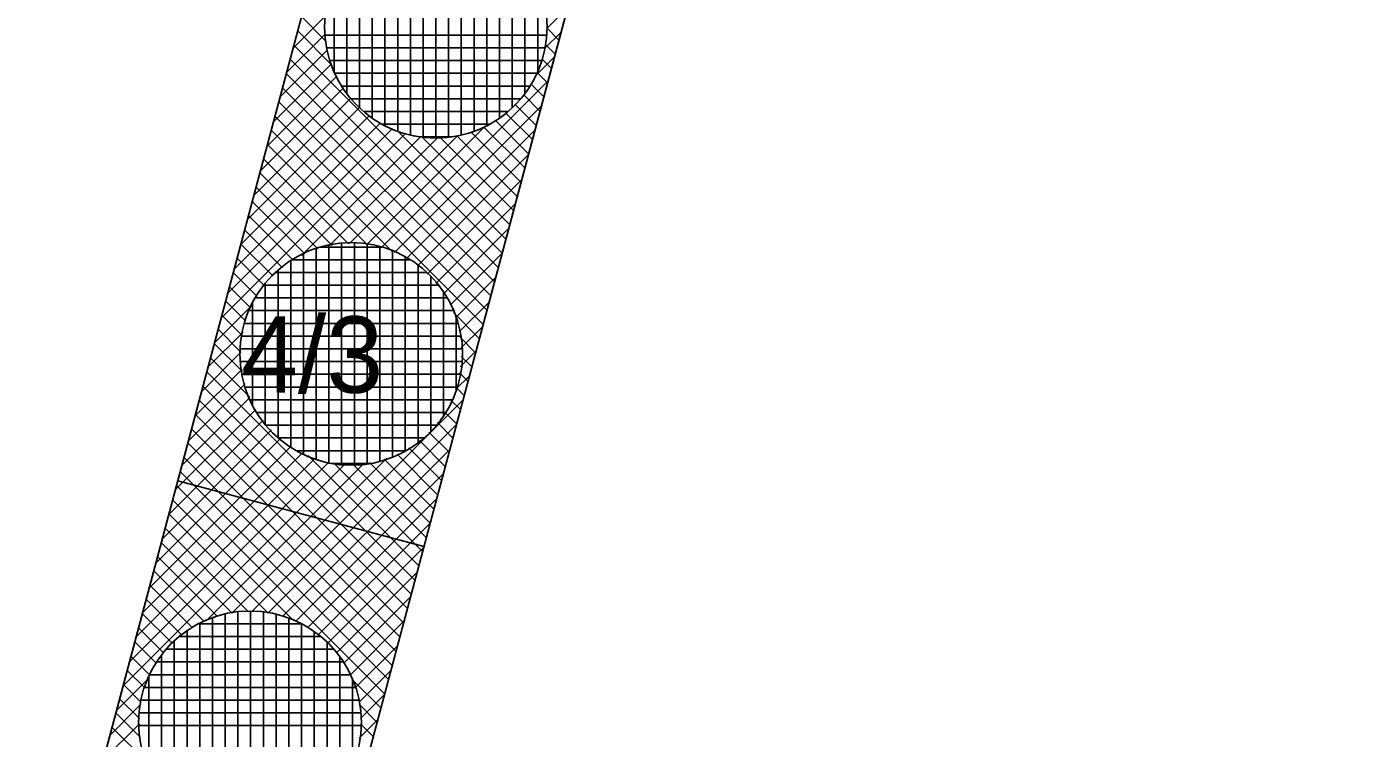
# Model space of a CAD drawing. Extents: x -566461 to -565198, y -1096301 to -1095707.
# Drawn here: x -565839.82 to -565818.76, y -1096050.3 to -1096039.12 of the extents above; entities that cross this region are included whole.
import ezdxf

# ---------------------------------------------------------------- set-up
doc = ezdxf.new("R2010")
doc.units = 0
for name, color, linetype in [('Vrstva 1', 7, 'Continuous'), ('Vrstva 40', 7, 'Continuous'), ('Vrstva 41', 7, 'Continuous'), ('Vrstva 42', 7, 'Continuous'), ('Vrstva 44', 7, 'Continuous')]:
    doc.layers.add(name, color=color, linetype=linetype)

msp = doc.modelspace()

# ---------------------------------------------------------------- linework, layer by layer
at = {"layer": 'Vrstva 1'}
for p, q in [((-565832.07, -1096026.09), (-565854, -1096108.33)), ((-565838.03, -1096063.98), (-565828.2, -1096027.12))]:
    msp.add_line(p, q, dxfattribs=at)
at = {"layer": 'Vrstva 41'}
for p, q in [((-565831.653, -1096039.151), (-565831.32, -1096038.818)), ((-565835.634, -1096039.455), (-565835.121, -1096038.942)), ((-565835.502, -1096038.96), (-565835.114, -1096039.348)), ((-565835.737, -1096039.84), (-565835.125, -1096039.228)), ((-565835.561, -1096039.183), (-565835.019, -1096039.726)), ((-565831.686, -1096039.467), (-565831.423, -1096039.203)), ((-565831.651, -1096039.133), (-565831.456, -1096039.329)), ((-565835.84, -1096040.226), (-565835.092, -1096039.479)), ((-565835.621, -1096039.407), (-565832.349, -1096042.678)), ((-565831.678, -1096039.389), (-565831.516, -1096039.552)), ((-565835.942, -1096040.612), (-565835.029, -1096039.699)), ((-565835.681, -1096039.63), (-565832.409, -1096042.901)), ((-565831.837, -1096039.901), (-565831.526, -1096039.589)), ((-565831.726, -1096039.625), (-565831.575, -1096039.775)), ((-565836.045, -1096040.998), (-565834.945, -1096039.897)), ((-565835.74, -1096039.853), (-565832.468, -1096043.125)), ((-565831.802, -1096039.832), (-565831.635, -1096039.999)), ((-565836.148, -1096041.383), (-565834.841, -1096040.076)), ((-565835.8, -1096040.076), (-565832.528, -1096043.348)), ((-565834.248, -1096042.594), (-565831.628, -1096039.975)), ((-565831.9, -1096040.016), (-565831.694, -1096040.222)), ((-565836.251, -1096041.769), (-565834.72, -1096040.238)), ((-565835.859, -1096040.3), (-565832.588, -1096043.571)), ((-565832.147, -1096040.334), (-565831.813, -1096040.669)), ((-565832.015, -1096040.184), (-565831.754, -1096040.445)), ((-565836.457, -1096042.54), (-565834.43, -1096040.514)), ((-565836.354, -1096042.155), (-565834.583, -1096040.384)), ((-565835.919, -1096040.523), (-565832.647, -1096043.795)), ((-565834.038, -1096042.667), (-565831.731, -1096040.361)), ((-565832.295, -1096040.47), (-565831.873, -1096040.892)), ((-565836.662, -1096043.312), (-565834.071, -1096040.72)), ((-565836.559, -1096042.926), (-565834.26, -1096040.627)), ((-565835.978, -1096040.746), (-565834.07, -1096042.655)), ((-565834.481, -1096042.545), (-565832.609, -1096040.673)), ((-565833.996, -1096040.749), (-565832.29, -1096042.455)), ((-565833.849, -1096042.761), (-565831.834, -1096040.746)), ((-565832.641, -1096040.689), (-565831.992, -1096041.338)), ((-565832.46, -1096040.588), (-565831.933, -1096041.115)), ((-565836.765, -1096043.697), (-565833.861, -1096040.793)), ((-565836.038, -1096040.97), (-565834.459, -1096042.549)), ((-565835.499, -1096042.714), (-565833.627, -1096040.842)), ((-565835.064, -1096042.561), (-565833.361, -1096040.859)), ((-565834.747, -1096042.527), (-565833.044, -1096040.825)), ((-565833.618, -1096040.844), (-565832.23, -1096042.232)), ((-565833.322, -1096040.857), (-565832.171, -1096042.008)), ((-565833.068, -1096040.828), (-565832.111, -1096041.785)), ((-565832.842, -1096040.771), (-565832.052, -1096041.562)), ((-565833.68, -1096042.875), (-565831.937, -1096041.132)), ((-565836.097, -1096041.193), (-565834.762, -1096042.528)), ((-565836.157, -1096041.416), (-565835.019, -1096042.554)), ((-565833.527, -1096043.005), (-565832.04, -1096041.518)), ((-565836.216, -1096041.64), (-565835.247, -1096042.609)), ((-565836.276, -1096041.863), (-565835.45, -1096042.689)), ((-565833.39, -1096043.151), (-565832.143, -1096041.903)), ((-565836.336, -1096042.086), (-565835.633, -1096042.789)), ((-565836.395, -1096042.309), (-565835.799, -1096042.906)), ((-565833.27, -1096043.314), (-565832.246, -1096042.289)), ((-565836.455, -1096042.533), (-565835.948, -1096043.04)), ((-565836.514, -1096042.756), (-565836.081, -1096043.189)), ((-565833.167, -1096043.494), (-565832.348, -1096042.675)), ((-565836.574, -1096042.979), (-565836.197, -1096043.356)), ((-565833.083, -1096043.692), (-565832.451, -1096043.061)), ((-565836.633, -1096043.203), (-565836.296, -1096043.54)), ((-565836.868, -1096044.083), (-565836.266, -1096043.481)), ((-565836.693, -1096043.426), (-565836.374, -1096043.744)), ((-565833.022, -1096043.914), (-565832.554, -1096043.446)), ((-565836.752, -1096043.649), (-565836.428, -1096043.974)), ((-565833.115, -1096043.61), (-565832.707, -1096044.018)), ((-565836.971, -1096044.469), (-565836.419, -1096043.916)), ((-565836.812, -1096043.873), (-565836.452, -1096044.232)), ((-565832.991, -1096044.166), (-565832.657, -1096043.832)), ((-565836.871, -1096044.096), (-565836.429, -1096044.538)), ((-565833.009, -1096043.999), (-565832.766, -1096044.241)), ((-565837.074, -1096044.854), (-565836.453, -1096044.233)), ((-565836.931, -1096044.319), (-565836.316, -1096044.934)), ((-565833.008, -1096044.465), (-565832.76, -1096044.218)), ((-565832.99, -1096044.3), (-565832.826, -1096044.464)), ((-565837.177, -1096045.24), (-565836.435, -1096044.499)), ((-565836.99, -1096044.542), (-565833.719, -1096047.814)), ((-565833.017, -1096044.556), (-565832.885, -1096044.688)), ((-565837.279, -1096045.626), (-565836.386, -1096044.732)), ((-565837.05, -1096044.766), (-565833.779, -1096048.037)), ((-565833.081, -1096044.821), (-565832.863, -1096044.603)), ((-565837.382, -1096046.012), (-565836.313, -1096044.942)), ((-565833.069, -1096044.787), (-565832.945, -1096044.911)), ((-565837.485, -1096046.397), (-565836.219, -1096045.131)), ((-565837.11, -1096044.989), (-565833.838, -1096048.26)), ((-565836.288, -1096048.311), (-565832.966, -1096044.989)), ((-565833.249, -1096045.173), (-565833.064, -1096045.358)), ((-565833.149, -1096044.99), (-565833.004, -1096045.134)), ((-565837.588, -1096046.783), (-565836.105, -1096045.3)), ((-565837.169, -1096045.212), (-565833.898, -1096048.484)), ((-565836.029, -1096048.335), (-565833.069, -1096045.375)), ((-565833.366, -1096045.339), (-565833.124, -1096045.581)), ((-565837.794, -1096047.554), (-565835.829, -1096045.59)), ((-565837.691, -1096047.169), (-565835.975, -1096045.453)), ((-565837.229, -1096045.436), (-565833.957, -1096048.707)), ((-565833.5, -1096045.488), (-565833.183, -1096045.804)), ((-565837.999, -1096048.326), (-565835.486, -1096045.813)), ((-565837.896, -1096047.94), (-565835.666, -1096045.71)), ((-565837.288, -1096045.659), (-565834.017, -1096048.93)), ((-565835.799, -1096048.388), (-565833.171, -1096045.761)), ((-565833.816, -1096045.737), (-565833.302, -1096046.251)), ((-565833.649, -1096045.621), (-565833.243, -1096046.028)), ((-565838.308, -1096049.483), (-565834.814, -1096045.989)), ((-565838.205, -1096049.097), (-565835.066, -1096045.958)), ((-565838.102, -1096048.711), (-565835.288, -1096045.897)), ((-565837.348, -1096045.882), (-565834.076, -1096049.154)), ((-565836.993, -1096048.45), (-565834.524, -1096045.982)), ((-565836.595, -1096048.336), (-565834.159, -1096045.899)), ((-565835.394, -1096045.856), (-565833.66, -1096047.591)), ((-565834.998, -1096045.969), (-565833.6, -1096047.367)), ((-565834.692, -1096045.992), (-565833.54, -1096047.144)), ((-565834.434, -1096045.968), (-565833.481, -1096046.921)), ((-565834.204, -1096045.914), (-565833.421, -1096046.697)), ((-565834, -1096045.836), (-565833.362, -1096046.474)), ((-565837.407, -1096046.106), (-565834.136, -1096049.377)), ((-565835.593, -1096048.465), (-565833.274, -1096046.146)), ((-565837.467, -1096046.329), (-565834.195, -1096049.6)), ((-565837.526, -1096046.552), (-565835.629, -1096048.45)), ((-565835.409, -1096048.563), (-565833.377, -1096046.532)), ((-565837.586, -1096046.775), (-565836.026, -1096048.335)), ((-565837.645, -1096046.999), (-565836.333, -1096048.311)), ((-565835.242, -1096048.679), (-565833.48, -1096046.918)), ((-565837.705, -1096047.222), (-565836.592, -1096048.335)), ((-565837.765, -1096047.445), (-565836.822, -1096048.388)), ((-565835.091, -1096048.812), (-565833.583, -1096047.303)), ((-565837.824, -1096047.669), (-565837.028, -1096048.465)), ((-565834.957, -1096048.96), (-565833.686, -1096047.689)), ((-565837.884, -1096047.892), (-565837.212, -1096048.564)), ((-565837.943, -1096048.115), (-565837.379, -1096048.679)), ((-565834.839, -1096049.125), (-565833.789, -1096048.075)), ((-565838.003, -1096048.339), (-565837.529, -1096048.812)), ((-565838.062, -1096048.562), (-565837.664, -1096048.96)), ((-565834.738, -1096049.307), (-565833.892, -1096048.461)), ((-565838.122, -1096048.785), (-565837.782, -1096049.125)), ((-565834.656, -1096049.508), (-565833.994, -1096048.846)), ((-565838.181, -1096049.008), (-565837.882, -1096049.307)), ((-565838.411, -1096049.868), (-565837.91, -1096049.367)), ((-565838.241, -1096049.232), (-565837.964, -1096049.509)), ((-565834.71, -1096049.369), (-565834.255, -1096049.823)), ((-565834.6, -1096049.735), (-565834.097, -1096049.232)), ((-565838.3, -1096049.455), (-565838.02, -1096049.736)), ((-565838.514, -1096050.254), (-565838.024, -1096049.765)), ((-565838.36, -1096049.678), (-565838.047, -1096049.991)), ((-565834.595, -1096049.766), (-565834.315, -1096050.047)), ((-565834.573, -1096049.99), (-565834.2, -1096049.618)), ((-565838.42, -1096049.902), (-565838.032, -1096050.289)), ((-565834.596, -1096050.296), (-565834.303, -1096050.003)), ((-565838.616, -1096050.64), (-565838.049, -1096050.072)), ((-565838.479, -1096050.125), (-565837.933, -1096050.671)), ((-565834.572, -1096050.072), (-565834.374, -1096050.27))]:
    msp.add_line(p, q, dxfattribs=at)
at = {"layer": 'Vrstva 42'}
msp.add_line((-565833.578, -1096047.286), (-565837.447, -1096046.255), dxfattribs=at)
msp.add_lwpolyline([(-565828.2, -1096027.12), (-565826.72, -1096023.51), (-565829.55, -1096025.32), (-565832.07, -1096026.09), (-565854, -1096108.33), (-565697.28, -1096140.23), (-565696.05, -1096136.4), (-565849.04, -1096105.26)], close=True, dxfattribs=at)
at = {"layer": 'Vrstva 44'}
for p, q in [((-565833.59, -1096040.858), (-565833.59, -1096037.383)), ((-565833.39, -1096040.868), (-565833.39, -1096037.371)), ((-565833.19, -1096040.857), (-565833.19, -1096037.382)), ((-565834.19, -1096040.676), (-565834.19, -1096037.564)), ((-565833.99, -1096040.762), (-565833.99, -1096037.477)), ((-565833.79, -1096040.823), (-565833.79, -1096037.418)), ((-565832.99, -1096040.822), (-565832.99, -1096037.418)), ((-565832.79, -1096040.764), (-565832.79, -1096037.478)), ((-565832.59, -1096040.675), (-565832.59, -1096037.565)), ((-565834.39, -1096040.554), (-565834.39, -1096037.686)), ((-565832.39, -1096040.554), (-565832.39, -1096037.686)), ((-565834.59, -1096040.393), (-565834.59, -1096037.847)), ((-565832.19, -1096040.392), (-565832.19, -1096037.848)), ((-565834.79, -1096040.167), (-565834.79, -1096038.072)), ((-565831.99, -1096040.17), (-565831.99, -1096038.073)), ((-565834.99, -1096039.828), (-565834.99, -1096038.415)), ((-565831.79, -1096039.824), (-565831.79, -1096038.412)), ((-565831.645, -1096039.25), (-565835.133, -1096039.25)), ((-565831.673, -1096039.45), (-565835.107, -1096039.45)), ((-565831.724, -1096039.65), (-565835.056, -1096039.65)), ((-565831.801, -1096039.85), (-565834.98, -1096039.85)), ((-565831.909, -1096040.05), (-565834.87, -1096040.05)), ((-565832.056, -1096040.25), (-565834.725, -1096040.25)), ((-565832.255, -1096040.45), (-565834.524, -1096040.45)), ((-565832.545, -1096040.65), (-565834.236, -1096040.65)), ((-565833.134, -1096040.85), (-565833.644, -1096040.85)), ((-565835.27, -1096045.919), (-565835.27, -1096042.601)), ((-565834.235, -1096042.58), (-565835.207, -1096042.58)), ((-565835.07, -1096045.973), (-565835.07, -1096042.547)), ((-565834.87, -1096046.002), (-565834.87, -1096042.517)), ((-565834.67, -1096046.007), (-565834.67, -1096042.512)), ((-565834.47, -1096045.991), (-565834.47, -1096042.53)), ((-565834.27, -1096045.951), (-565834.27, -1096042.571)), ((-565834.07, -1096045.883), (-565834.07, -1096042.636)), ((-565835.67, -1096045.73), (-565835.67, -1096042.792)), ((-565833.789, -1096042.78), (-565835.653, -1096042.78)), ((-565835.47, -1096045.839), (-565835.47, -1096042.68)), ((-565833.87, -1096045.788), (-565833.87, -1096042.732)), ((-565833.67, -1096045.66), (-565833.67, -1096042.862)), ((-565833.529, -1096042.98), (-565835.913, -1096042.98)), ((-565835.87, -1096045.576), (-565835.87, -1096042.943)), ((-565833.47, -1096045.482), (-565833.47, -1096043.037)), ((-565833.345, -1096043.18), (-565836.095, -1096043.18)), ((-565836.07, -1096045.371), (-565836.07, -1096043.149)), ((-565833.27, -1096045.236), (-565833.27, -1096043.281)), ((-565836.27, -1096045.068), (-565836.27, -1096043.452)), ((-565833.209, -1096043.38), (-565836.232, -1096043.38)), ((-565833.108, -1096043.58), (-565836.33, -1096043.58)), ((-565833.07, -1096044.839), (-565833.07, -1096043.681)), ((-565833.039, -1096043.78), (-565836.401, -1096043.78)), ((-565832.994, -1096043.98), (-565836.447, -1096043.98)), ((-565832.973, -1096044.18), (-565836.467, -1096044.18)), ((-565832.974, -1096044.38), (-565836.464, -1096044.38)), ((-565833.001, -1096044.58), (-565836.438, -1096044.58)), ((-565833.051, -1096044.78), (-565836.389, -1096044.78)), ((-565833.127, -1096044.98), (-565836.315, -1096044.98)), ((-565833.232, -1096045.18), (-565836.206, -1096045.18)), ((-565833.378, -1096045.38), (-565836.063, -1096045.38)), ((-565833.573, -1096045.58), (-565835.866, -1096045.58)), ((-565833.856, -1096045.78), (-565835.583, -1096045.78)), ((-565834.404, -1096045.98), (-565835.032, -1096045.98)), ((-565836.7, -1096051.756), (-565836.7, -1096048.346)), ((-565836.5, -1096051.789), (-565836.5, -1096048.312)), ((-565836.3, -1096051.798), (-565836.3, -1096048.301)), ((-565836.1, -1096051.785), (-565836.1, -1096048.313)), ((-565835.9, -1096051.75), (-565835.9, -1096048.351)), ((-565835.499, -1096048.5), (-565837.12, -1096048.5)), ((-565837.1, -1096051.611), (-565837.1, -1096048.489)), ((-565836.9, -1096051.696), (-565836.9, -1096048.404)), ((-565835.7, -1096051.69), (-565835.7, -1096048.412)), ((-565835.5, -1096051.599), (-565835.5, -1096048.5)), ((-565837.5, -1096051.332), (-565837.5, -1096048.767)), ((-565835.197, -1096048.7), (-565837.421, -1096048.7)), ((-565837.3, -1096051.491), (-565837.3, -1096048.609)), ((-565835.3, -1096051.477), (-565835.3, -1096048.623)), ((-565834.993, -1096048.9), (-565837.628, -1096048.9)), ((-565835.1, -1096051.312), (-565835.1, -1096048.787)), ((-565834.842, -1096049.1), (-565837.777, -1096049.1)), ((-565837.7, -1096051.11), (-565837.7, -1096048.989)), ((-565834.9, -1096051.085), (-565834.9, -1096049.016)), ((-565837.9, -1096050.78), (-565837.9, -1096049.32)), ((-565834.731, -1096049.3), (-565837.891, -1096049.3)), ((-565834.7, -1096050.731), (-565834.7, -1096049.366)), ((-565834.649, -1096049.5), (-565837.97, -1096049.5)), ((-565834.597, -1096049.7), (-565838.023, -1096049.7)), ((-565834.568, -1096049.9), (-565838.052, -1096049.9)), ((-565834.563, -1096050.1), (-565838.058, -1096050.1))]:
    msp.add_line(p, q, dxfattribs=at)
for centre in [(-565833.39, -1096039.12), (-565834.72, -1096044.26), (-565836.31, -1096050.05)]:
    msp.add_circle(centre, 1.75, dxfattribs=at)

# ---------------------------------------------------------------- texts
at = {"layer": 'Vrstva 40'}
msp.add_text('4/3', height=1.2, dxfattribs=at).set_placement((-565836.45, -1096044.87))

doc.saveas('drawing.dxf')
